// Mitsubishi GX Works2 project: 8.两灯交替闪烁   PLC: FX3U/FX3UC

PROGRAM MAIN
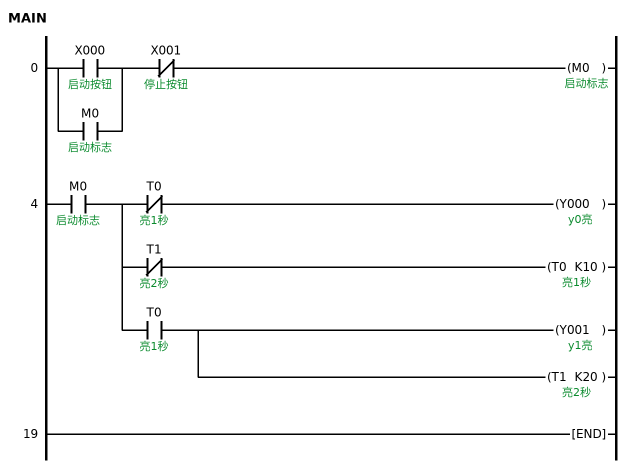
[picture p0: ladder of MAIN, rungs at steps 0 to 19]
0     LD      X000  ; 启动按钮
      OR      M0  ; 启动标志
      ANI     X001  ; 停止按钮
      OUT     M0  ; 启动标志
4     LD      M0  ; 启动标志
      MPS
      ANI     T0  ; 亮1秒
      OUT     Y000  ; y0亮
      MRD
      ANI     T1  ; 亮2秒
      OUT     T0 K10  ; 亮1秒
      MPP
      AND     T0  ; 亮1秒
      OUT     Y001  ; y1亮
      OUT     T1 K20  ; 亮2秒
19    END
END_PROGRAM
